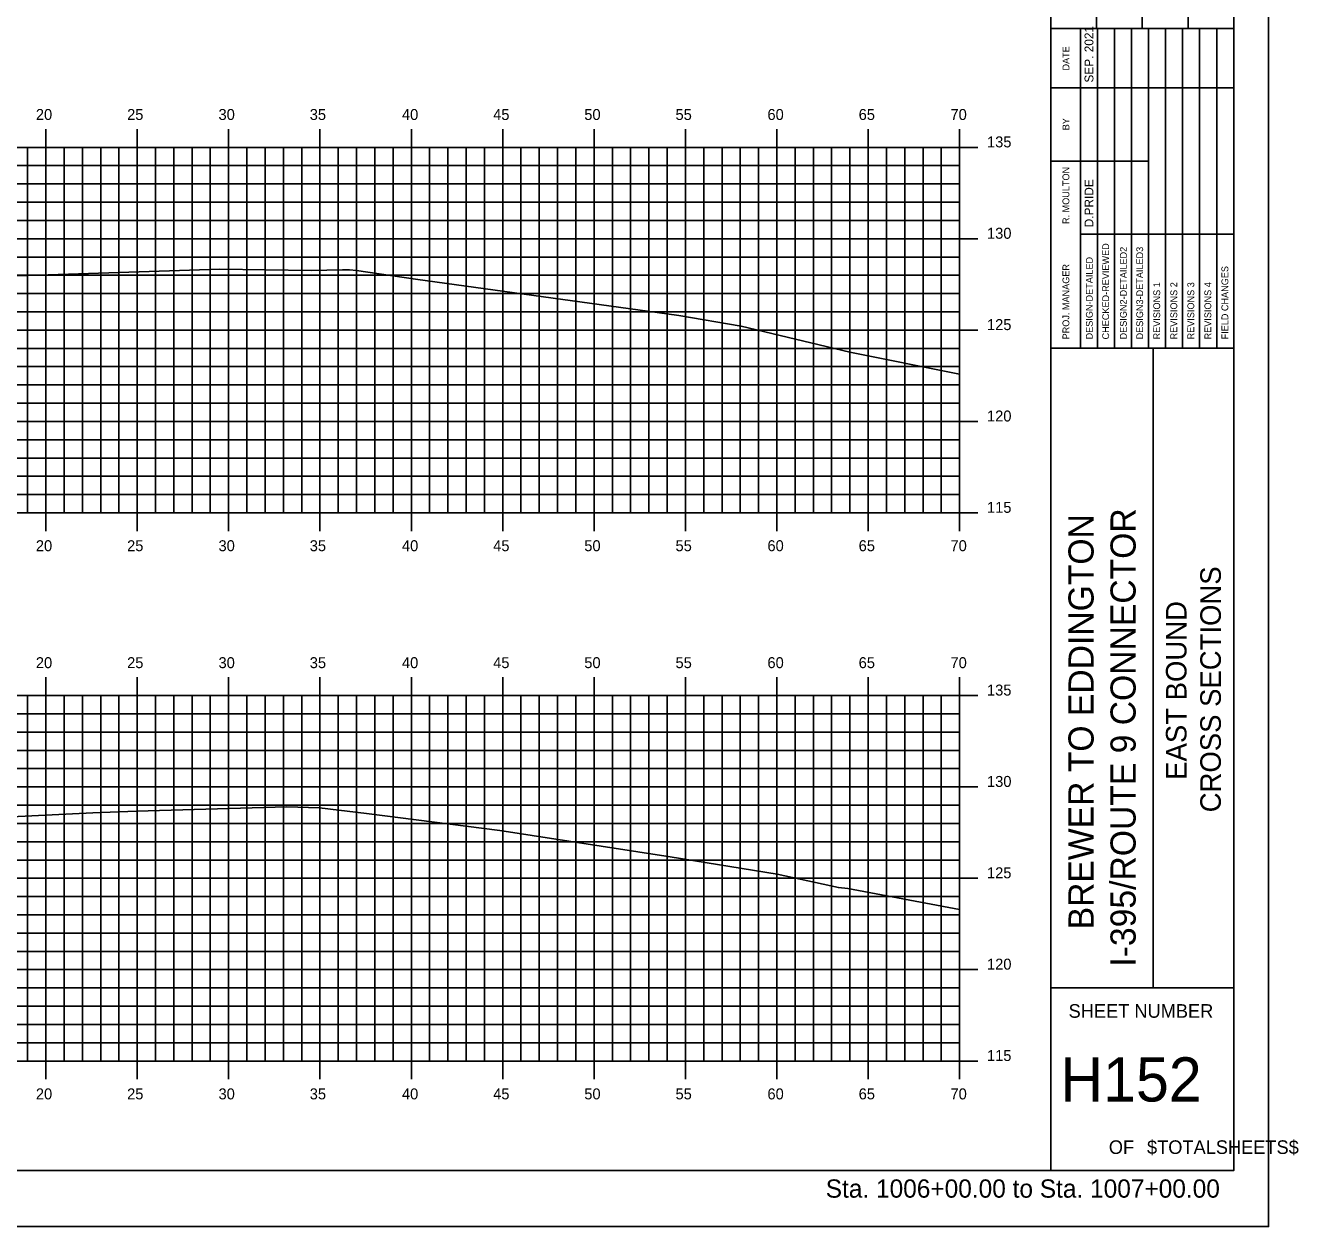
# Model space of a CAD drawing. Extents: x 851517 to 851688, y 365624 to 365734.
# Drawn here: x 851618.7 to 851688.3, y 365624 to 365689.7 of the extents above; entities that cross this region are included whole.
import ezdxf

# ---------------------------------------------------------------- set-up
doc = ezdxf.new("R2010")
doc.units = 0
for name, color, linetype in [('BORDER', 7, 'Continuous'), ('H_V ANNOTATION', 7, 'Continuous'), ('MAJOR', 7, 'Continuous'), ('MINOR', 7, 'Continuous'), ('PLOT BOUNDARY', 7, 'Continuous'), ('S_Roadway_Centerline', 7, 'Continuous')]:
    doc.layers.add(name, color=color, linetype=linetype)

msp = doc.modelspace()

# ---------------------------------------------------------------- linework, layer by layer
at = {"layer": 'BORDER'}
for p, q in [((851674.766, 365627.027), (851674.766, 365732.027)), ((851677.266, 365689.53), (851677.266, 365698.177)), ((851679.766, 365689.53), (851679.766, 365698.177)), ((851682.266, 365689.53), (851682.266, 365698.177)), ((851674.766, 365689.53), (851684.766, 365689.53)), ((851674.766, 365672.03), (851684.766, 365672.03)), ((851680.357, 365637.03), (851680.357, 365672.03)), ((851674.766, 365637.03), (851684.766, 365637.03))]:
    msp.add_line(p, q, dxfattribs=at)
msp.add_lwpolyline([(851524.766, 365627.027), (851684.766, 365627.027), (851684.766, 365732.027), (851524.766, 365732.027)], close=True, dxfattribs=at)
for points in [[(851676.381, 365686.28), (851676.381, 365689.53)], [(851677.313, 365672.033), (851677.313, 365689.53)], [(851678.245, 365689.53), (851678.245, 365672.033)], [(851679.177, 365672.033), (851679.177, 365689.53)], [(851680.108, 365672.033), (851680.108, 365689.53)], [(851681.04, 365672.033), (851681.04, 365689.53)], [(851681.972, 365672.033), (851681.972, 365689.53)], [(851682.903, 365672.033), (851682.903, 365689.53)], [(851683.835, 365672.033), (851683.835, 365689.53)], [(851676.382, 365672.033), (851676.382, 365688.824)], [(851674.766, 365686.28), (851684.766, 365686.28)], [(851674.766, 365682.28), (851676.382, 365682.28)], [(851676.381, 365682.28), (851680.107, 365682.28)], [(851676.381, 365678.28), (851684.766, 365678.28)]]:
    msp.add_lwpolyline(points, dxfattribs=at)
at = {"layer": 'MAJOR'}
for p, q in [((851619.766, 365684.029), (851619.766, 365683.027)), ((851624.766, 365684.029), (851624.766, 365683.027)), ((851629.766, 365684.029), (851629.766, 365683.027)), ((851634.766, 365684.029), (851634.766, 365683.027)), ((851639.766, 365684.029), (851639.766, 365683.027)), ((851644.766, 365684.029), (851644.766, 365683.027)), ((851649.766, 365684.029), (851649.766, 365683.027)), ((851654.766, 365684.029), (851654.766, 365683.027)), ((851659.766, 365684.029), (851659.766, 365683.027)), ((851664.766, 365684.029), (851664.766, 365683.027)), ((851669.766, 365684.029), (851669.766, 365683.027)), ((851529.766, 365683.027), (851669.766, 365683.027)), ((851529.766, 365683.027), (851669.766, 365683.027)), ((851619.766, 365663.027), (851619.766, 365683.027)), ((851624.766, 365663.027), (851624.766, 365683.027)), ((851629.766, 365663.027), (851629.766, 365683.027)), ((851634.766, 365663.027), (851634.766, 365683.027)), ((851639.766, 365663.027), (851639.766, 365683.027)), ((851644.766, 365663.027), (851644.766, 365683.027)), ((851649.766, 365663.027), (851649.766, 365683.027)), ((851654.766, 365663.027), (851654.766, 365683.027)), ((851659.766, 365663.027), (851659.766, 365683.027)), ((851664.766, 365663.027), (851664.766, 365683.027)), ((851670.768, 365683.027), (851668.764, 365683.027)), ((851669.766, 365663.027), (851669.766, 365683.027)), ((851669.766, 365663.027), (851669.766, 365683.027)), ((851529.766, 365678.027), (851669.766, 365678.027)), ((851670.768, 365678.027), (851668.764, 365678.027)), ((851529.766, 365673.027), (851669.766, 365673.027)), ((851670.768, 365673.027), (851668.764, 365673.027)), ((851529.766, 365668.027), (851669.766, 365668.027)), ((851670.768, 365668.027), (851668.764, 365668.027)), ((851529.766, 365663.027), (851669.766, 365663.027)), ((851529.766, 365663.027), (851669.766, 365663.027)), ((851619.766, 365662.025), (851619.766, 365663.027)), ((851624.766, 365662.025), (851624.766, 365663.027)), ((851629.766, 365662.025), (851629.766, 365663.027)), ((851634.766, 365662.025), (851634.766, 365663.027)), ((851639.766, 365662.025), (851639.766, 365663.027)), ((851644.766, 365662.025), (851644.766, 365663.027)), ((851649.766, 365662.025), (851649.766, 365663.027)), ((851654.766, 365662.025), (851654.766, 365663.027)), ((851659.766, 365662.025), (851659.766, 365663.027)), ((851664.766, 365662.025), (851664.766, 365663.027)), ((851670.768, 365663.027), (851668.764, 365663.027)), ((851669.766, 365662.025), (851669.766, 365663.027)), ((851619.766, 365654.029), (851619.766, 365653.027)), ((851624.766, 365654.029), (851624.766, 365653.027)), ((851629.766, 365654.029), (851629.766, 365653.027)), ((851634.766, 365654.029), (851634.766, 365653.027)), ((851639.766, 365654.029), (851639.766, 365653.027)), ((851644.766, 365654.029), (851644.766, 365653.027)), ((851649.766, 365654.029), (851649.766, 365653.027)), ((851654.766, 365654.029), (851654.766, 365653.027)), ((851659.766, 365654.029), (851659.766, 365653.027)), ((851664.766, 365654.029), (851664.766, 365653.027)), ((851669.766, 365654.029), (851669.766, 365653.027)), ((851529.766, 365653.027), (851669.766, 365653.027)), ((851529.766, 365653.027), (851669.766, 365653.027)), ((851619.766, 365633.027), (851619.766, 365653.027)), ((851624.766, 365633.027), (851624.766, 365653.027)), ((851629.766, 365633.027), (851629.766, 365653.027)), ((851634.766, 365633.027), (851634.766, 365653.027)), ((851639.766, 365633.027), (851639.766, 365653.027)), ((851644.766, 365633.027), (851644.766, 365653.027)), ((851649.766, 365633.027), (851649.766, 365653.027)), ((851654.766, 365633.027), (851654.766, 365653.027)), ((851659.766, 365633.027), (851659.766, 365653.027)), ((851664.766, 365633.027), (851664.766, 365653.027)), ((851670.768, 365653.027), (851668.764, 365653.027)), ((851669.766, 365633.027), (851669.766, 365653.027)), ((851669.766, 365633.027), (851669.766, 365653.027)), ((851529.766, 365648.027), (851669.766, 365648.027)), ((851670.768, 365648.027), (851668.764, 365648.027)), ((851529.766, 365643.027), (851669.766, 365643.027)), ((851670.768, 365643.027), (851668.764, 365643.027)), ((851529.766, 365638.027), (851669.766, 365638.027)), ((851670.768, 365638.027), (851668.764, 365638.027)), ((851529.766, 365633.027), (851669.766, 365633.027)), ((851529.766, 365633.027), (851669.766, 365633.027)), ((851619.766, 365632.025), (851619.766, 365633.027)), ((851624.766, 365632.025), (851624.766, 365633.027)), ((851629.766, 365632.025), (851629.766, 365633.027)), ((851634.766, 365632.025), (851634.766, 365633.027)), ((851639.766, 365632.025), (851639.766, 365633.027)), ((851644.766, 365632.025), (851644.766, 365633.027)), ((851649.766, 365632.025), (851649.766, 365633.027)), ((851654.766, 365632.025), (851654.766, 365633.027)), ((851659.766, 365632.025), (851659.766, 365633.027)), ((851664.766, 365632.025), (851664.766, 365633.027)), ((851670.768, 365633.027), (851668.764, 365633.027)), ((851669.766, 365632.025), (851669.766, 365633.027))]:
    msp.add_line(p, q, dxfattribs=at)
at = {"layer": 'MINOR'}
for p, q in [((851618.766, 365663.027), (851618.766, 365683.027)), ((851620.766, 365663.027), (851620.766, 365683.027)), ((851621.766, 365663.027), (851621.766, 365683.027)), ((851622.766, 365663.027), (851622.766, 365683.027)), ((851623.766, 365663.027), (851623.766, 365683.027)), ((851625.766, 365663.027), (851625.766, 365683.027)), ((851626.766, 365663.027), (851626.766, 365683.027)), ((851627.766, 365663.027), (851627.766, 365683.027)), ((851628.766, 365663.027), (851628.766, 365683.027)), ((851630.766, 365663.027), (851630.766, 365683.027)), ((851631.766, 365663.027), (851631.766, 365683.027)), ((851632.766, 365663.027), (851632.766, 365683.027)), ((851633.766, 365663.027), (851633.766, 365683.027)), ((851635.766, 365663.027), (851635.766, 365683.027)), ((851636.766, 365663.027), (851636.766, 365683.027)), ((851637.766, 365663.027), (851637.766, 365683.027)), ((851638.766, 365663.027), (851638.766, 365683.027)), ((851640.766, 365663.027), (851640.766, 365683.027)), ((851641.766, 365663.027), (851641.766, 365683.027)), ((851642.766, 365663.027), (851642.766, 365683.027)), ((851643.766, 365663.027), (851643.766, 365683.027)), ((851645.766, 365663.027), (851645.766, 365683.027)), ((851646.766, 365663.027), (851646.766, 365683.027)), ((851647.766, 365663.027), (851647.766, 365683.027)), ((851648.766, 365663.027), (851648.766, 365683.027)), ((851650.766, 365663.027), (851650.766, 365683.027)), ((851651.766, 365663.027), (851651.766, 365683.027)), ((851652.766, 365663.027), (851652.766, 365683.027)), ((851653.766, 365663.027), (851653.766, 365683.027)), ((851655.766, 365663.027), (851655.766, 365683.027)), ((851656.766, 365663.027), (851656.766, 365683.027)), ((851657.766, 365663.027), (851657.766, 365683.027)), ((851658.766, 365663.027), (851658.766, 365683.027)), ((851660.766, 365663.027), (851660.766, 365683.027)), ((851661.766, 365663.027), (851661.766, 365683.027)), ((851662.766, 365663.027), (851662.766, 365683.027)), ((851663.766, 365663.027), (851663.766, 365683.027)), ((851665.766, 365663.027), (851665.766, 365683.027)), ((851666.766, 365663.027), (851666.766, 365683.027)), ((851667.766, 365663.027), (851667.766, 365683.027)), ((851668.766, 365663.027), (851668.766, 365683.027)), ((851529.766, 365682.027), (851669.766, 365682.027)), ((851669.766, 365682.027), (851668.764, 365682.027)), ((851529.766, 365681.027), (851669.766, 365681.027)), ((851669.766, 365681.027), (851668.764, 365681.027)), ((851529.766, 365680.027), (851669.766, 365680.027)), ((851669.766, 365680.027), (851668.764, 365680.027)), ((851529.766, 365679.027), (851669.766, 365679.027)), ((851669.766, 365679.027), (851668.764, 365679.027)), ((851529.766, 365677.027), (851669.766, 365677.027)), ((851669.766, 365677.027), (851668.764, 365677.027)), ((851529.766, 365676.027), (851669.766, 365676.027)), ((851669.766, 365676.027), (851668.764, 365676.027)), ((851529.766, 365675.027), (851669.766, 365675.027)), ((851669.766, 365675.027), (851668.764, 365675.027)), ((851529.766, 365674.027), (851669.766, 365674.027)), ((851669.766, 365674.027), (851668.764, 365674.027)), ((851529.766, 365672.027), (851669.766, 365672.027)), ((851669.766, 365672.027), (851668.764, 365672.027)), ((851529.766, 365671.027), (851669.766, 365671.027)), ((851669.766, 365671.027), (851668.764, 365671.027)), ((851529.766, 365670.027), (851669.766, 365670.027)), ((851669.766, 365670.027), (851668.764, 365670.027)), ((851529.766, 365669.027), (851669.766, 365669.027)), ((851669.766, 365669.027), (851668.764, 365669.027)), ((851529.766, 365667.027), (851669.766, 365667.027)), ((851669.766, 365667.027), (851668.764, 365667.027)), ((851529.766, 365666.027), (851669.766, 365666.027)), ((851669.766, 365666.027), (851668.764, 365666.027)), ((851529.766, 365665.027), (851669.766, 365665.027)), ((851669.766, 365665.027), (851668.764, 365665.027)), ((851529.766, 365664.027), (851669.766, 365664.027)), ((851669.766, 365664.027), (851668.764, 365664.027)), ((851618.766, 365633.027), (851618.766, 365653.027)), ((851620.766, 365633.027), (851620.766, 365653.027)), ((851621.766, 365633.027), (851621.766, 365653.027)), ((851622.766, 365633.027), (851622.766, 365653.027)), ((851623.766, 365633.027), (851623.766, 365653.027)), ((851625.766, 365633.027), (851625.766, 365653.027)), ((851626.766, 365633.027), (851626.766, 365653.027)), ((851627.766, 365633.027), (851627.766, 365653.027)), ((851628.766, 365633.027), (851628.766, 365653.027)), ((851630.766, 365633.027), (851630.766, 365653.027)), ((851631.766, 365633.027), (851631.766, 365653.027)), ((851632.766, 365633.027), (851632.766, 365653.027)), ((851633.766, 365633.027), (851633.766, 365653.027)), ((851635.766, 365633.027), (851635.766, 365653.027)), ((851636.766, 365633.027), (851636.766, 365653.027)), ((851637.766, 365633.027), (851637.766, 365653.027)), ((851638.766, 365633.027), (851638.766, 365653.027)), ((851640.766, 365633.027), (851640.766, 365653.027)), ((851641.766, 365633.027), (851641.766, 365653.027)), ((851642.766, 365633.027), (851642.766, 365653.027)), ((851643.766, 365633.027), (851643.766, 365653.027)), ((851645.766, 365633.027), (851645.766, 365653.027)), ((851646.766, 365633.027), (851646.766, 365653.027)), ((851647.766, 365633.027), (851647.766, 365653.027)), ((851648.766, 365633.027), (851648.766, 365653.027)), ((851650.766, 365633.027), (851650.766, 365653.027)), ((851651.766, 365633.027), (851651.766, 365653.027)), ((851652.766, 365633.027), (851652.766, 365653.027)), ((851653.766, 365633.027), (851653.766, 365653.027)), ((851655.766, 365633.027), (851655.766, 365653.027)), ((851656.766, 365633.027), (851656.766, 365653.027)), ((851657.766, 365633.027), (851657.766, 365653.027)), ((851658.766, 365633.027), (851658.766, 365653.027)), ((851660.766, 365633.027), (851660.766, 365653.027)), ((851661.766, 365633.027), (851661.766, 365653.027)), ((851662.766, 365633.027), (851662.766, 365653.027)), ((851663.766, 365633.027), (851663.766, 365653.027)), ((851665.766, 365633.027), (851665.766, 365653.027)), ((851666.766, 365633.027), (851666.766, 365653.027)), ((851667.766, 365633.027), (851667.766, 365653.027)), ((851668.766, 365633.027), (851668.766, 365653.027)), ((851529.766, 365652.027), (851669.766, 365652.027)), ((851669.766, 365652.027), (851668.764, 365652.027)), ((851529.766, 365651.027), (851669.766, 365651.027)), ((851669.766, 365651.027), (851668.764, 365651.027)), ((851529.766, 365650.027), (851669.766, 365650.027)), ((851669.766, 365650.027), (851668.764, 365650.027)), ((851529.766, 365649.027), (851669.766, 365649.027)), ((851669.766, 365649.027), (851668.764, 365649.027)), ((851529.766, 365647.027), (851669.766, 365647.027)), ((851669.766, 365647.027), (851668.764, 365647.027)), ((851529.766, 365646.027), (851669.766, 365646.027)), ((851669.766, 365646.027), (851668.764, 365646.027)), ((851529.766, 365645.027), (851669.766, 365645.027)), ((851669.766, 365645.027), (851668.764, 365645.027)), ((851529.766, 365644.027), (851669.766, 365644.027)), ((851669.766, 365644.027), (851668.764, 365644.027)), ((851529.766, 365642.027), (851669.766, 365642.027)), ((851669.766, 365642.027), (851668.764, 365642.027)), ((851529.766, 365641.027), (851669.766, 365641.027)), ((851669.766, 365641.027), (851668.764, 365641.027)), ((851529.766, 365640.027), (851669.766, 365640.027)), ((851669.766, 365640.027), (851668.764, 365640.027)), ((851529.766, 365639.027), (851669.766, 365639.027)), ((851669.766, 365639.027), (851668.764, 365639.027)), ((851529.766, 365637.027), (851669.766, 365637.027)), ((851669.766, 365637.027), (851668.764, 365637.027)), ((851529.766, 365636.027), (851669.766, 365636.027)), ((851669.766, 365636.027), (851668.764, 365636.027)), ((851529.766, 365635.027), (851669.766, 365635.027)), ((851669.766, 365635.027), (851668.764, 365635.027)), ((851529.766, 365634.027), (851669.766, 365634.027)), ((851669.766, 365634.027), (851668.764, 365634.027))]:
    msp.add_line(p, q, dxfattribs=at)
at = {"layer": 'PLOT BOUNDARY'}
msp.add_lwpolyline([(851516.673, 365623.968), (851686.673, 365623.968), (851686.673, 365733.968), (851516.673, 365733.968)], close=True, dxfattribs=at)
at = {"layer": 'S_Roadway_Centerline'}
for points in [[(851616.963, 365675.958), (851619.897, 365676.055), (851629.285, 365676.362), (851634.277, 365676.288), (851635.995, 365676.331), (851636.388, 365676.328), (851636.767, 365676.284), (851639.986, 365675.815), (851654.398, 365673.824), (851657.816, 365673.24), (851663.76, 365671.813), (851669.766, 365670.622)], [(851615.634, 365646.285), (851622.334, 365646.606), (851624.727, 365646.702), (851632.961, 365646.929), (851634.732, 365646.882), (851637.313, 365646.568), (851644.605, 365645.645), (851653.93, 365644.196), (851659.788, 365643.26), (851663.133, 365642.516), (851663.642, 365642.473), (851669.766, 365641.321)]]:
    msp.add_lwpolyline(points, dxfattribs=at)

# ---------------------------------------------------------------- texts
at = {"layer": 'BORDER'}
for s, height, p in [('SEP. 2021', 0.4845, (851677.089, 365686.575)), ('DATE', 0.3714, (851675.77, 365687.235)), ('BY', 0.3714, (851675.77, 365683.965)), ('R. MOULTON', 0.3727, (851675.77, 365678.832)), ('D.PRIDE', 0.4845, (851677.089, 365678.653)), ('CHECKED-REVIEWED', 0.37275, (851677.947, 365672.518)), ('DESIGN2-DETAILED2', 0.37275, (851678.916, 365672.518)), ('DESIGN3-DETAILED3', 0.37275, (851679.81, 365672.518)), ('DESIGN-DETAILED', 0.37275, (851677.052, 365672.518)), ('PROJ. MANAGER', 0.37275, (851675.77, 365672.518)), ('FIELD CHANGES', 0.37275, (851684.469, 365672.518)), ('REVISIONS 1', 0.37275, (851680.742, 365672.518)), ('REVISIONS 2', 0.37275, (851681.674, 365672.518)), ('REVISIONS 3', 0.37275, (851682.605, 365672.518)), ('REVISIONS 4', 0.37275, (851683.537, 365672.518)), ('BREWER TO EDDINGTON', 1.37787, (851677.1, 365640.231)), ('I-395/ROUTE 9 CONNECTOR', 1.37787, (851679.401, 365638.192)), ('CROSS SECTIONS', 1.125, (851684.063, 365646.638)), ('EAST BOUND', 1.125, (851682.184, 365648.418))]:
    msp.add_text(s, height=height, rotation=90, dxfattribs=at).set_placement(p)
for s, height, p in [('SHEET NUMBER', 0.74527, (851675.731, 365635.393)), ('H152', 2.4194, (851675.281, 365630.809)), ('OF', 0.7453, (851677.933, 365627.94)), ('$TOTALSHEETS$', 0.74527, (851680.022, 365627.94))]:
    msp.add_text(s, height=height, dxfattribs=at).set_placement(p)
at = {"layer": 'H_V ANNOTATION'}
for s, height, p in [('20', 0.6, (851619.22, 365684.527)), ('25', 0.6, (851624.212, 365684.527)), ('30', 0.6, (851629.214, 365684.527)), ('35', 0.6, (851634.206, 365684.527)), ('40', 0.6, (851639.252, 365684.527)), ('45', 0.6, (851644.244, 365684.527)), ('50', 0.6, (851649.23, 365684.527)), ('55', 0.6, (851654.222, 365684.527)), ('60', 0.6, (851659.252, 365684.527)), ('65', 0.6, (851664.244, 365684.527)), ('70', 0.6, (851669.268, 365684.527)), ('135', 0.6, (851671.266, 365683.027)), ('130', 0.6, (851671.266, 365678.027)), ('125', 0.6, (851671.266, 365673.027)), ('120', 0.6, (851671.266, 365668.027)), ('115', 0.6, (851671.266, 365663.027)), ('20', 0.6, (851619.22, 365660.927)), ('25', 0.6, (851624.212, 365660.927)), ('30', 0.6, (851629.214, 365660.927)), ('35', 0.6, (851634.206, 365660.927)), ('40', 0.6, (851639.252, 365660.927)), ('45', 0.6, (851644.244, 365660.927)), ('50', 0.6, (851649.23, 365660.927)), ('55', 0.6, (851654.222, 365660.927)), ('60', 0.6, (851659.252, 365660.927)), ('65', 0.6, (851664.244, 365660.927)), ('70', 0.6, (851669.268, 365660.927)), ('20', 0.6, (851619.22, 365654.527)), ('25', 0.6, (851624.212, 365654.527)), ('30', 0.6, (851629.214, 365654.527)), ('35', 0.6, (851634.206, 365654.527)), ('40', 0.6, (851639.252, 365654.527)), ('45', 0.6, (851644.244, 365654.527)), ('50', 0.6, (851649.23, 365654.527)), ('55', 0.6, (851654.222, 365654.527)), ('60', 0.6, (851659.252, 365654.527)), ('65', 0.6, (851664.244, 365654.527)), ('70', 0.6, (851669.268, 365654.527)), ('135', 0.6, (851671.266, 365653.027)), ('130', 0.6, (851671.266, 365648.027)), ('125', 0.6, (851671.266, 365643.027)), ('120', 0.6, (851671.266, 365638.027)), ('115', 0.6, (851671.266, 365633.027)), ('20', 0.6, (851619.22, 365630.927)), ('25', 0.6, (851624.212, 365630.927)), ('30', 0.6, (851629.214, 365630.927)), ('35', 0.6, (851634.206, 365630.927)), ('40', 0.6, (851639.252, 365630.927)), ('45', 0.6, (851644.244, 365630.927)), ('50', 0.6, (851649.23, 365630.927)), ('55', 0.6, (851654.222, 365630.927)), ('60', 0.6, (851659.252, 365630.927)), ('65', 0.6, (851664.244, 365630.927)), ('70', 0.6, (851669.268, 365630.927)), ('Sta. 1006+00.00 to Sta. 1007+00.00', 1.0002, (851662.442, 365625.547))]:
    msp.add_text(s, height=height, dxfattribs=at).set_placement(p)

doc.saveas('drawing.dxf')
